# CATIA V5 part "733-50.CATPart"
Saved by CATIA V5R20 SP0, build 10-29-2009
Part number: 733-50
Bounding box of the stored display mesh (mm): x -40 to 40, y -40 to 40, z -47 to 80
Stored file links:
  C:\Users\Utente\Desktop\IO LAVORO\3D X SITO CF\X SITO\733\733-50.CATPart
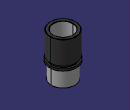
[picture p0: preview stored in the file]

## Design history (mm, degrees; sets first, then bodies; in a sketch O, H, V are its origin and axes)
Set1
  DatumSurface1 to DatumSurface25 "733-50"
Body1 (main body)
